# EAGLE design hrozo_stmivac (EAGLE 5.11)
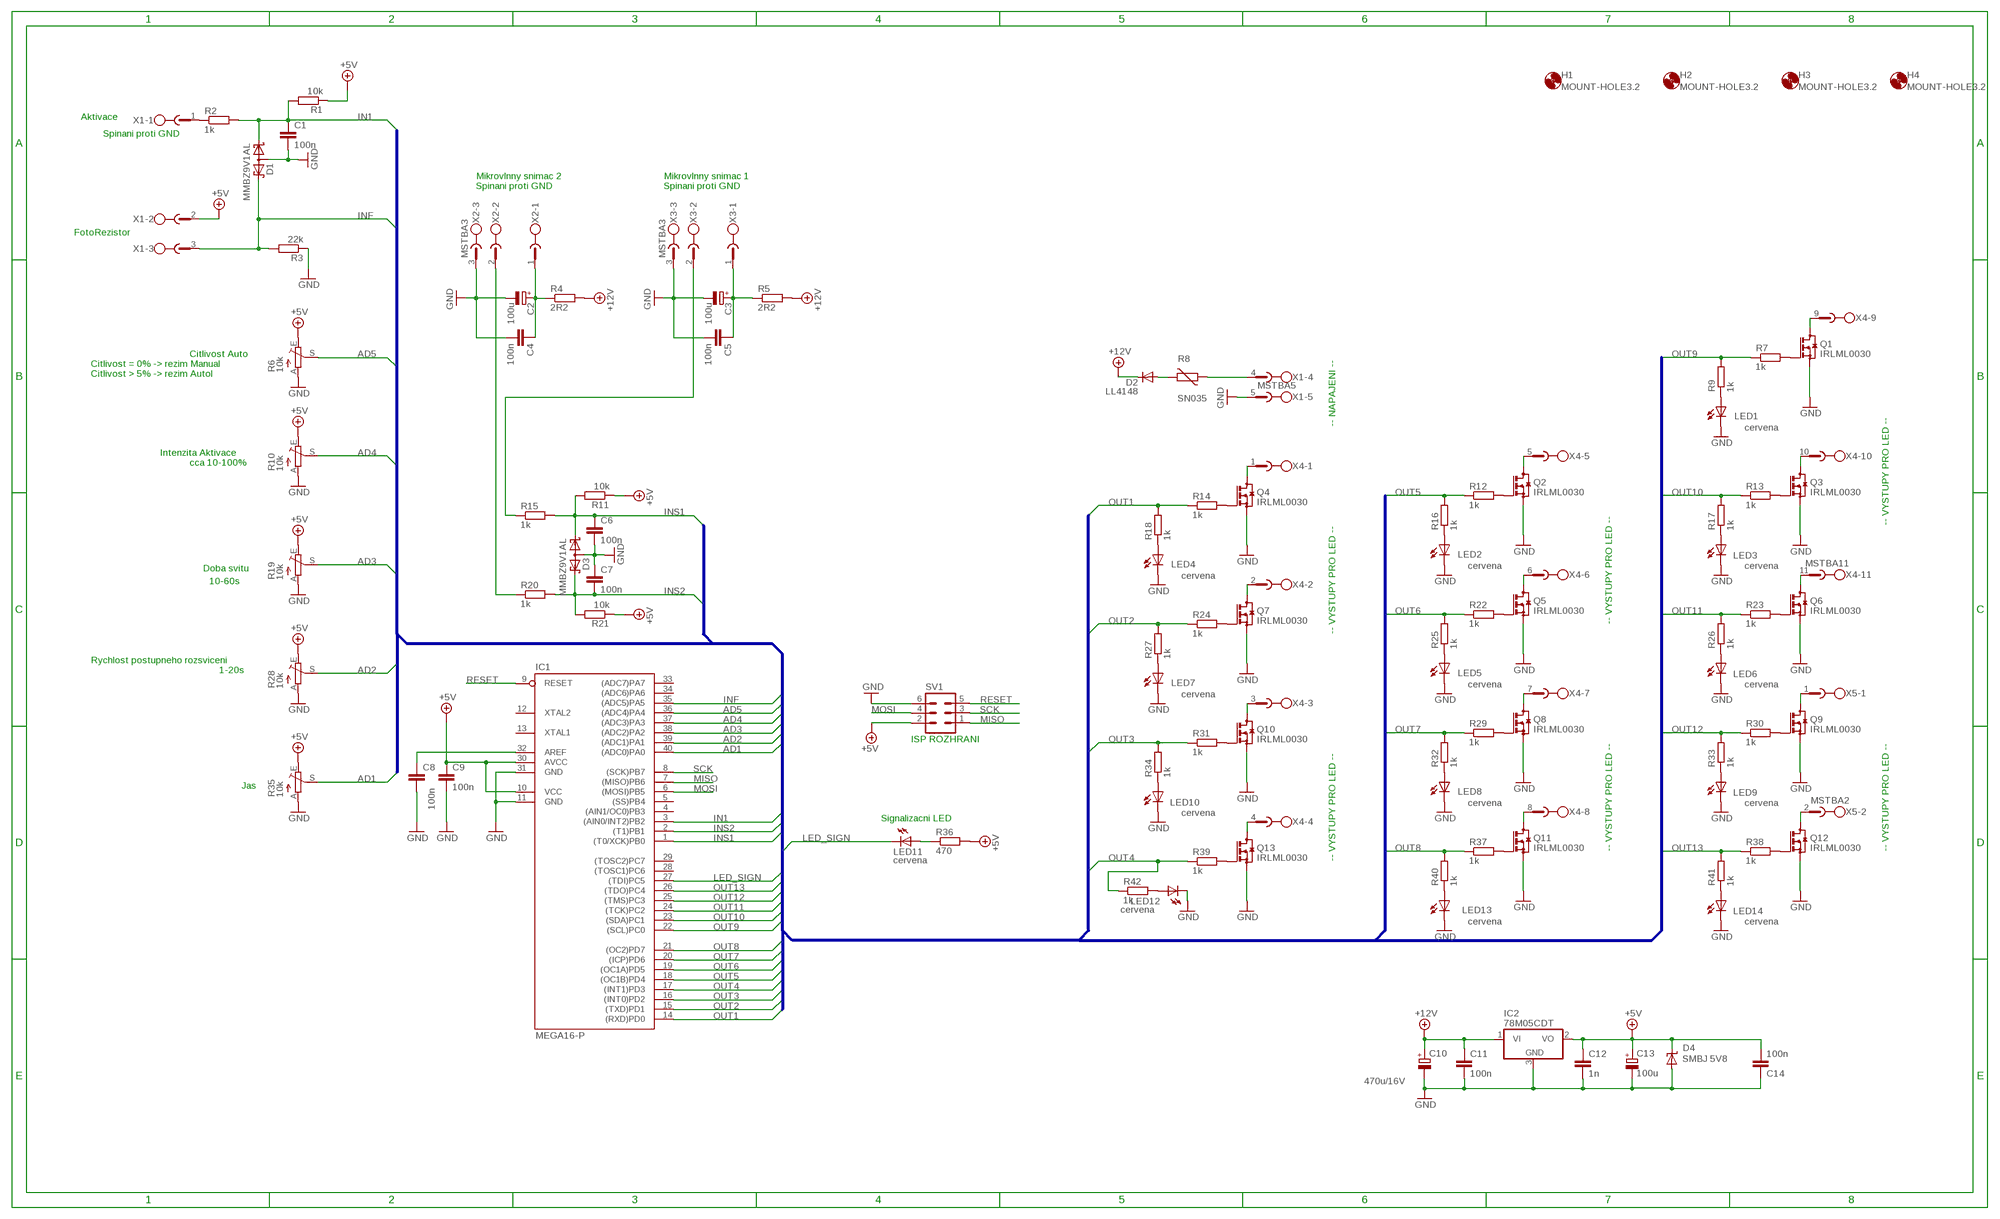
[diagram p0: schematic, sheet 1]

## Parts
C1  100n  C-EUC0805K  [C0805K]
C2  100u  CPOL-EUE2.5-5  [E2,5-5]
C3  100u  CPOL-EUE2.5-5  [E2,5-5]
C4  100n  C-EUC0805K  [C0805K]
C5  100n  C-EUC0805K  [C0805K]
C6  100n  C-EUC0805K  [C0805K]
C7  100n  C-EUC0805K  [C0805K]
C8  100n  C-EUC0805K  [C0805K]
C9  100n  C-EUC0805K  [C0805K]
C10  470u/16V  CPOL-EUE5-10.5  [E5-10,5]
C11  100n  C-EUC1206  [C1206]
C12  1n  C-EUC0805K  [C0805K]
C13  100u  CPOL-EUE2.5-5  [E2,5-5]
C14  100n  C-EUC0805  [C0805]
D1  MMBZ9V1AL  BAS40-06  [SOT23]
D2  LL4148  DIODE-MINIMELF  [MINIMELF]
D3  MMBZ9V1AL  BAS40-06  [SOT23]
D4  SMBJ 5V8  SUPPRESSOR-SMBJ  [SMBJ]
H1  MOUNT-HOLE3.2  [3,2]
H2  MOUNT-HOLE3.2  [3,2]
H3  MOUNT-HOLE3.2  [3,2]
H4  MOUNT-HOLE3.2  [3,2]
IC1  MEGA16-P  [DIL40]
IC2  78M05CDT  7805DT  [TO252]
LED1  cervena  LEDCHIPLED_0805  [CHIPLED_0805]
LED2  cervena  LEDCHIPLED_0805  [CHIPLED_0805]
LED3  cervena  LEDCHIPLED_0805  [CHIPLED_0805]
LED4  cervena  LEDCHIPLED_0805  [CHIPLED_0805]
LED5  cervena  LEDCHIPLED_0805  [CHIPLED_0805]
LED6  cervena  LEDCHIPLED_0805  [CHIPLED_0805]
LED7  cervena  LEDCHIPLED_0805  [CHIPLED_0805]
LED8  cervena  LEDCHIPLED_0805  [CHIPLED_0805]
LED9  cervena  LEDCHIPLED_0805  [CHIPLED_0805]
LED10  cervena  LEDCHIPLED_0805  [CHIPLED_0805]
LED11  cervena  LED3MM  [LED3MM]
LED12  cervena  LEDCHIPLED_0805  [CHIPLED_0805]
LED13  cervena  LEDCHIPLED_0805  [CHIPLED_0805]
LED14  cervena  LEDCHIPLED_0805  [CHIPLED_0805]
Q1  IRLML0030  BSS123  [SOT23]
Q2  IRLML0030  BSS123  [SOT23]
Q3  IRLML0030  BSS123  [SOT23]
Q4  IRLML0030  BSS123  [SOT23]
Q5  IRLML0030  BSS123  [SOT23]
Q6  IRLML0030  BSS123  [SOT23]
Q7  IRLML0030  BSS123  [SOT23]
Q8  IRLML0030  BSS123  [SOT23]
Q9  IRLML0030  BSS123  [SOT23]
Q10  IRLML0030  BSS123  [SOT23]
Q11  IRLML0030  BSS123  [SOT23]
Q12  IRLML0030  BSS123  [SOT23]
Q13  IRLML0030  BSS123  [SOT23]
R1  10k  R-EU_R0805  [R0805]
R2  1k  R-EU_R0805  [R0805]
R3  22k  R-EU_R0805  [R0805]
R4  2R2  R-EU_M1206  [M1206]
R5  2R2  R-EU_M1206  [M1206]
R6  10k  TRIM_EU-CA9V  [CA9V]
R7  1k  R-EU_R0805  [R0805]
R8  SN035  VARISTORCN1206  [CT/CN1206]
R9  1k  R-EU_R0805  [R0805]
R10  10k  TRIM_EU-CA9V  [CA9V]
R11  10k  R-EU_R0805  [R0805]
R12  1k  R-EU_R0805  [R0805]
R13  1k  R-EU_R0805  [R0805]
R14  1k  R-EU_R0805  [R0805]
R15  1k  R-EU_R0805  [R0805]
R16  1k  R-EU_R0805  [R0805]
R17  1k  R-EU_R0805  [R0805]
R18  1k  R-EU_R0805  [R0805]
R19  10k  TRIM_EU-CA9V  [CA9V]
R20  1k  R-EU_R0805  [R0805]
R21  10k  R-EU_R0805  [R0805]
R22  1k  R-EU_R0805  [R0805]
R23  1k  R-EU_R0805  [R0805]
R24  1k  R-EU_R0805  [R0805]
R25  1k  R-EU_R0805  [R0805]
R26  1k  R-EU_R0805  [R0805]
R27  1k  R-EU_R0805  [R0805]
R28  10k  TRIM_EU-CA9V  [CA9V]
R29  1k  R-EU_R0805  [R0805]
R30  1k  R-EU_R0805  [R0805]
R31  1k  R-EU_R0805  [R0805]
R32  1k  R-EU_R0805  [R0805]
R33  1k  R-EU_R0805  [R0805]
R34  1k  R-EU_R0805  [R0805]
R35  10k  TRIM_EU-CA9V  [CA9V]
R36  470  R-EU_R0805  [R0805]
R37  1k  R-EU_R0805  [R0805]
R38  1k  R-EU_R0805  [R0805]
R39  1k  R-EU_R0805  [R0805]
R40  1k  R-EU_R0805  [R0805]
R41  1k  R-EU_R0805  [R0805]
R42  1k  R-EU_R0805  [R0805]
SV1  MA03-2  [MA03-2]
X1  MSTBA5  [MSTBA5]
X2  MSTBA3  [MSTBA3]
X3  MSTBA3  [MSTBA3]
X4  MSTBA11  [MSTBA11]
X5  MSTBA2  [MSTBA2]

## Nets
+5V: C9.1 C12.1 C13.+ C14.2 D4.C IC1.10(VCC) IC1.30(AVCC) IC2.2(VO) R1.1 R6.E R10.E R11.1 R19.E R21.1 R28.E R35.E R36.2 SV1.2 X1.2
+12V: C10.+ C11.1 D2.C IC2.1(VI) R4.2 R5.2
AD1: IC1.40((ADC0)PA0) R35.S
AD2: IC1.39((ADC1)PA1) R28.S
AD3: IC1.38((ADC2)PA2) R19.S
AD4: IC1.37((ADC3)PA3) R10.S
AD5: IC1.36((ADC4)PA4) R6.S
GND: C1.2 C2.- C3.- C4.2 C5.2 C6.2 C7.1 C8.2 C9.2 C10.- C11.2 C12.2 C13.- C14.1 D1.3(AA) D3.3(AA) D4.A IC1.11(GND) IC1.31(GND) IC2.3(GND) LED1.C LED2.C LED3.C LED4.C LED5.C LED6.C LED7.C LED8.C LED9.C LED10.C LED12.C LED13.C LED14.C Q1.2(S) Q2.2(S) Q3.2(S) Q4.2(S) Q5.2(S) Q6.2(S) Q7.2(S) Q8.2(S) Q9.2(S) Q10.2(S) Q11.2(S) Q12.2(S) Q13.2(S) R3.1 R6.A R10.A R19.A R28.A R35.A SV1.6 X1.5 X2.3 X3.3
IN1: C1.1 D1.1(K1) IC1.3((AIN0/INT2)PB2) R1.2 R2.2
INF: D1.2(K2) IC1.35((ADC5)PA5) R3.2 X1.3
INS1: C6.1 D3.1(K1) IC1.1((T0/XCK)PB0) R11.2 R15.2
INS2: C7.2 D3.2(K2) IC1.2((T1)PB1) R20.2 R21.2
LED_SIGN: IC1.27((TDI)PC5) LED11.K(C)
MISO: IC1.7((MISO)PB6) SV1.1
MOSI: IC1.6((MOSI)PB5) SV1.4
N$1: R8.1 X1.4
N$2: Q4.3(D) X4.1
N$3: Q4.1(G) R14.2
N$4: Q7.1(G) R24.2
N$5: Q10.1(G) R31.2
N$6: Q13.1(G) R39.2
N$7: Q7.3(D) X4.2
N$8: Q10.3(D) X4.3
N$9: Q13.3(D) X4.4
N$10: R2.1 X1.1
N$11: R15.1 X3.2
N$12: R20.1 X2.2
N$13: LED7.A R27.1
N$14: LED12.A R42.2
N$15: D2.A R8.2
N$16: C8.1 IC1.32(AREF)
N$17: LED4.A R18.1
N$18: Q2.3(D) X4.5
N$19: Q2.1(G) R12.2
N$20: Q5.1(G) R22.2
N$21: Q8.1(G) R29.2
N$22: Q11.1(G) R37.2
N$23: Q5.3(D) X4.6
N$24: Q8.3(D) X4.7
N$25: Q11.3(D) X4.8
N$26: Q3.3(D) X4.10
N$27: Q3.1(G) R13.2
N$28: Q6.1(G) R23.2
N$29: Q9.1(G) R30.2
N$30: Q12.1(G) R38.2
N$31: Q6.3(D) X4.11
N$32: Q9.3(D) X5.1
N$33: Q12.3(D) X5.2
N$34: Q1.3(D) X4.9
N$35: Q1.1(G) R7.2
N$36: LED10.A R34.1
N$37: LED2.A R16.1
N$38: C2.+ C4.1 R4.1 X2.1
N$39: C3.+ C5.1 R5.1 X3.1
N$41: LED5.A R25.1
N$42: LED8.A R32.1
N$43: LED13.A R40.1
N$44: LED1.A R9.1
N$45: LED3.A R17.1
N$46: LED6.A R26.1
N$47: LED9.A R33.1
N$50: LED14.A R41.1
N$56: LED11.A R36.1
OUT1: IC1.14((RXD)PD0) R14.1 R18.2
OUT2: IC1.15((TXD)PD1) R24.1 R27.2
OUT3: IC1.16((INT0)PD2) R31.1 R34.2
OUT4: IC1.17((INT1)PD3) R39.1 R42.1
OUT5: IC1.18((OC1B)PD4) R12.1 R16.2
OUT6: IC1.19((OC1A)PD5) R22.1 R25.2
OUT7: IC1.20((ICP)PD6) R29.1 R32.2
OUT8: IC1.21((OC2)PD7) R37.1 R40.2
OUT9: IC1.22((SCL)PC0) R7.1 R9.2
OUT10: IC1.23((SDA)PC1) R13.1 R17.2
OUT11: IC1.24((TCK)PC2) R23.1 R26.2
OUT12: IC1.25((TMS)PC3) R30.1 R33.2
OUT13: IC1.26((TDO)PC4) R38.1 R41.2
RESET: IC1.9(RESET) SV1.5
SCK: IC1.8((SCK)PB7) SV1.3
Unconnected: IC1.4((AIN1/OC0)PB3) IC1.5((SS)PB4) IC1.12(XTAL2) IC1.13(XTAL1) IC1.28((TOSC1)PC6) IC1.29((TOSC2)PC7) IC1.33((ADC7)PA7) IC1.34((ADC6)PA6)

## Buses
OUT[1..13],IN[1..2],INS[1..2],BTN_KEYFOB,BTN_COMB,MOSI-OUT4,LED_SIGN,INF,AD[1..5]

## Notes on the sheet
- Aktivace
- Spinani proti GND
- Mikrovlnny snimac 2 | Mikrovlnny snimac 1
- Spinani proti GND | Spinani proti GND
- FotoRezistor
- Citlivost Auto
- Citlivost = 0% -> rezim Manual
- Citlivost > 5% -> rezim Autol
- -- NAPAJENI --
- Intenzita Aktivace
- cca 10-100%
- -- VYSTUPY PRO LED --
- Doba svitu
- 10-60s
- -- VYSTUPY PRO LED --
- -- VYSTUPY PRO LED --
- Rychlost postupneho rozsviceni
- 1-20s
- ISP ROZHRANI
- Jas
- Signalizacni LED
- -- VYSTUPY PRO LED -- | -- VYSTUPY PRO LED --
- -- VYSTUPY PRO LED --

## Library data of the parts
C1 C4-C9 C11 C12 C14 = rcl:C-EU: CAPACITOR, European symbol
C2 C3 C10 C13 = rcl:CPOL-EU: POLARIZED CAPACITOR, European symbol
D1 D3 = diode:BAS40-06: Silicon Schottky Diodes General-purpose diode for high-speed switching
D2 = diode:DIODE-: DIODE
D4 = diode:SUPPRESSOR-: Suppressor diode
H1-H4 = holes:MOUNT-HOLE: MOUNTING HOLE with drill center marker
IC1 = atmel:MEGA16-P: MICROCONTROLLER 16 Kbytes FLASH 1 kbytes SRAM 512 bytes EEPROM USART 8-channel 10 bit ADC Source: avr.lbr
IC2 = linear:78*: Positive VOLTAGE REGULATOR Source: http://cache.national.com/ds/LM/LM78L05.pdf http://www.fairchildsemi.com/ds/LM/LM7805.pdf
LED1-LED14 = led:LED: LED
Q1-Q13 = transistor-small-signal:BSS123: N-CHANNEL MOS FET
R1-R5 R7 R9 R11-R18 R20-R27 R29-R34 R36-R42 = rcl:R-EU_: RESISTOR, European symbol
R6 R10 R19 R28 R35 = pot:TRIM_EU-: POTENTIOMETER
R8 = varistor:VARISTOR: VARISTOR
SV1 = con-lstb:MA03-2: PIN HEADER
X1 = con-phoenix-508:MSTBA5: PHOENIX
X2 X3 = con-phoenix-508:MSTBA3: PHOENIX
X4 = con-phoenix-508:MSTBA11: PHOENIX
X5 = con-phoenix-508:MSTBA2: PHOENIX

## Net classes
2 ant: clearance 2 mm

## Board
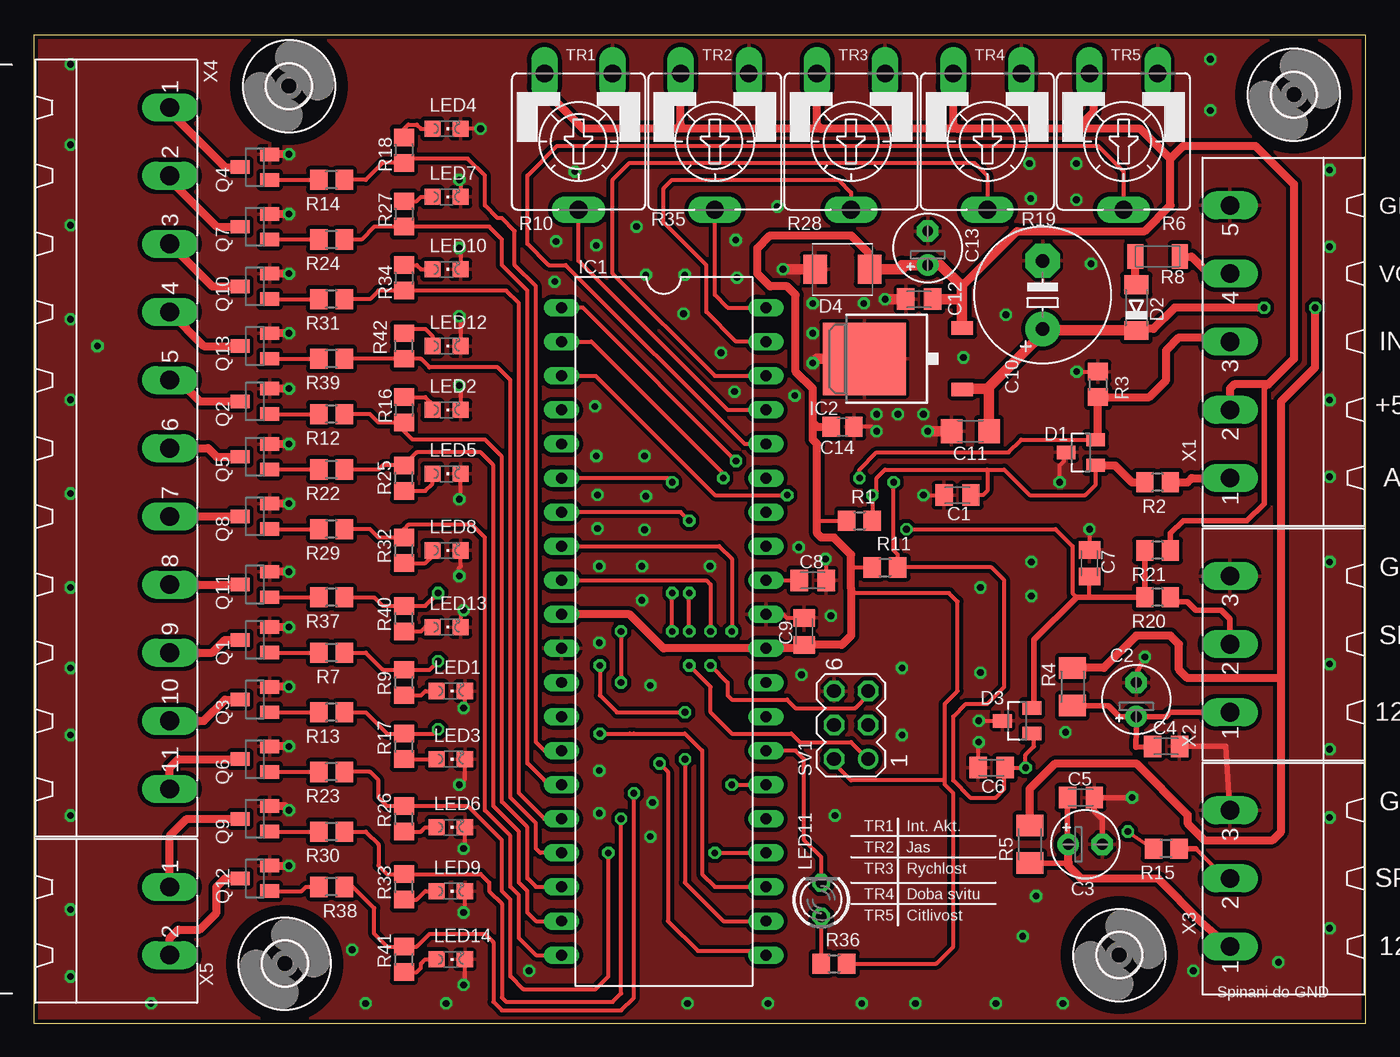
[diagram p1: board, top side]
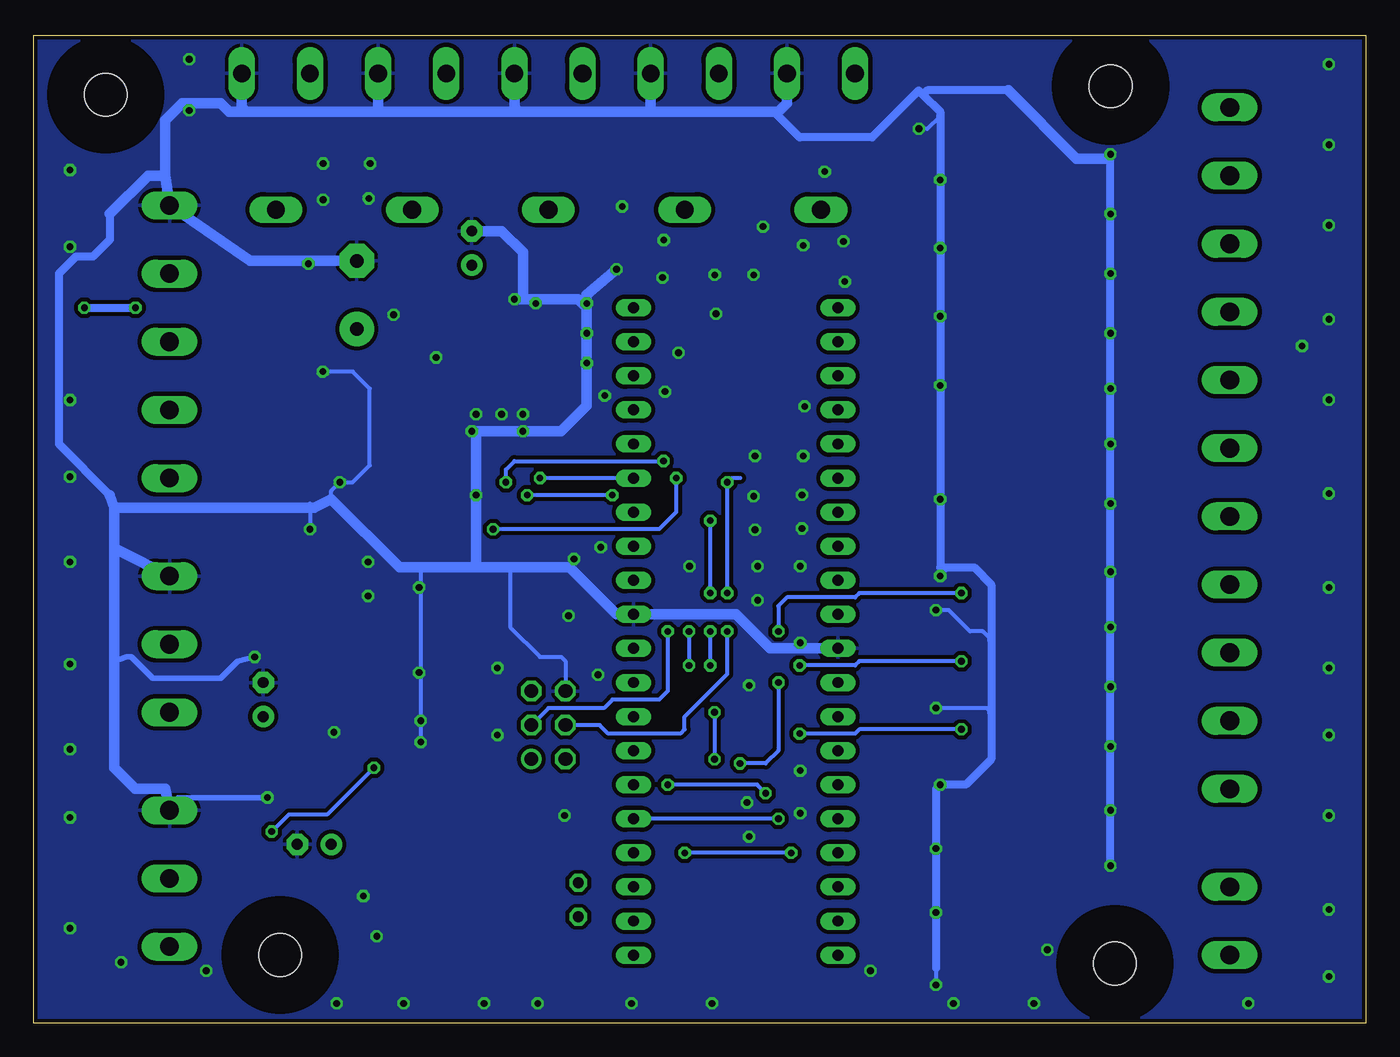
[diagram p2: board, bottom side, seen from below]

Size 99.36 x 73.65 mm. Coordinates in mm from the lower left corner, seen from the top.
Outline: 0,0 99.36,0 99.36,73.65 0,73.65 0,0
Copper layers (1*16): Top 0.035mm / dielectric 1.5mm / Bottom 0.035mm
Design rules "default *": minimum track width 0.17mm, minimum drill 0.4mm, track to track 0.2mm, track to pad 0.2mm, pad to pad 0.2mm, via to via 0.2mm, smd to smd 0.2mm, copper to edge 0.3mm, drill to drill 8mil, minimum pad ring 10mil, minimum via ring 8mil, stop-mask expansion 4mil, vias tented up to drill 0mil, thermal gap 10mil

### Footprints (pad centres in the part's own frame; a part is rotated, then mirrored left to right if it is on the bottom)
C0805K = smd 1.3 x 1.6: 1 -1,0; 2 1,0
E2,5-5 = drill 0.813 pad 1.6 round: + -1.27,0 | drill 0.813 pad 1.6 octagon: - 1.27,0
E5-10,5 = drill 1.016 pad 2.54 round: + -2.54,0 | drill 1.016 pad 2.54 octagon: - 2.54,0
C1206 = smd 1.6 x 1.8: 1 -1.4,0; 2 1.4,0
C0805 = smd 1.3 x 1.5: 1 -0.85,0; 2 0.85,0
SOT23 = smd 1 x 1.4: 1 -0.95,-1.1; 2 0.95,-1.1; 3 0,1.1
MINIMELF = smd 1.4 x 1.8: A 1.7,0; C -1.7,0
SMBJ = smd 1.78 x 2.16: A 2.04,0; C -2.03,0
3,2 = hole 3.2: 0,0
DIL40 = drill 0.813 long: 1 -24.13,-7.62; 2 -21.59,-7.62; 3 -19.05,-7.62; 4 -16.51,-7.62; 5 -13.97,-7.62; 6 -11.43,-7.62; 7 -8.89,-7.62; 8 -6.35,-7.62; 9 -3.81,-7.62; 10 -1.27,-7.62; 11 1.27,-7.62; 12 3.81,-7.62; 13 6.35,-7.62; 14 8.89,-7.62; 15 11.43,-7.62; 16 13.97,-7.62; 17 16.51,-7.62; 18 19.05,-7.62; 19 21.59,-7.62; 20 24.13,-7.62; 21 24.13,7.62; 22 21.59,7.62; 23 19.05,7.62; 24 16.51,7.62; 25 13.97,7.62; 26 11.43,7.62; 27 8.89,7.62; 28 6.35,7.62; 29 3.81,7.62; 30 1.27,7.62; 31 -1.27,7.62; 32 -3.81,7.62; 33 -6.35,7.62; 34 -8.89,7.62; 35 -11.43,7.62; 36 -13.97,7.62; 37 -16.51,7.62; 38 -19.05,7.62; 39 -21.59,7.62; 40 -24.13,7.62
TO252 = smd 1 x 1.6: 1 -2.28,-4.8; 2 2.28,-4.8 | smd 5.4 x 6.2: 3 0,2.5
CHIPLED_0805 = smd 1.2 x 1.2: A 0,-1.05; C 0,1.05
LED3MM = drill 0.813 octagon: A -1.27,0; K 1.27,0
R0805 = smd 1.3 x 1.5: 1 -0.95,0; 2 0.95,0
M1206 = smd 1.6 x 2: 1 -1.4,0; 2 1.4,0
CA9V = drill 1.321 long: A -2.54,-5.08; E 2.54,-5.08; S 0,5.08
CT/CN1206 = smd 1.2 x 1.8: 1 -1.65,0; 2 1.65,0
MA03-2 = drill 1.016 round: 1 -2.54,-1.27 | drill 1.016 octagon: 2 -2.54,1.27; 3 0,-1.27; 4 0,1.27; 5 2.54,-1.27; 6 2.54,1.27
MSTBA5 = drill 1.397 long: 1 -10.16,5.08; 2 -5.08,5.08; 3 0,5.08; 4 5.08,5.08; 5 10.16,5.08
MSTBA3 = drill 1.397 long: 1 -5.08,5.08; 2 0,5.08; 3 5.08,5.08
MSTBA11 = drill 1.397 long: 1 -25.4,5.08; 2 -20.32,5.08; 3 -15.24,5.08; 4 -10.16,5.08; 5 -5.08,5.08; 6 0,5.08; 7 5.08,5.08; 8 10.16,5.08; 9 15.24,5.08; 10 20.32,5.08; 11 25.4,5.08
MSTBA2 = drill 1.397 long: 1 -2.54,5.08; 2 2.54,5.08

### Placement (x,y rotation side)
C1  68.9,39.37 180 top
C2  82.23,24.13 90 top
C3  78.42,13.33 0 top
C4  84.45,20.64 0 top
C5  78.11,16.83 0 top
C6  71.44,19.05 180 top
C7  78.74,34.29 270 top
C8  58.1,33.02 0 top
C9  57.47,29.21 90 top
C10  75.25,54.29 90 top
C11  69.85,44.13 180 top
C12  66.04,53.97 180 top
C13  66.67,57.78 90 top
C14  60.33,44.45 180 top
D1  78.11,42.54 90 top
D2  82.23,53.34 90 top
D3  73.34,22.54 90 top
D4  60.33,56.2 180 top
H1  19.05,69.85 0 top
H2  18.73,4.45 0 top
H3  93.98,69.22 0 top
H4  80.96,5.08 0 top
IC1  46.99,29.21 270 top
IC2  64.45,49.53 90 top
LED1  31.12,24.77 270 top
LED2  30.8,45.72 270 top
LED3  31.12,19.69 270 top
LED4  30.8,66.68 270 top
LED5  30.8,40.96 270 top
LED6  31.12,14.6 270 top
LED7  30.8,61.59 270 top
LED8  30.8,35.24 270 top
LED9  31.12,9.84 270 top
LED10  30.8,56.2 270 top
LED11  58.74,9.21 90 top
LED12  30.8,50.48 270 top
LED13  30.8,29.53 270 top
LED14  31.12,4.76 270 top
Q1  16.51,28.57 90 top
Q2  16.51,46.35 90 top
Q3  16.51,24.13 90 top
Q4  16.51,63.82 90 top
Q5  16.51,42.23 90 top
Q6  16.51,19.69 90 top
Q7  16.51,59.37 90 top
Q8  16.51,37.78 90 top
Q9  16.51,15.24 90 top
Q10  16.51,54.93 90 top
Q11  16.51,32.7 90 top
Q12  16.51,10.79 90 top
Q13  16.51,50.48 90 top
R1  61.59,37.46 0 top
R2  83.82,40.32 180 top
R3  79.38,47.62 270 top
R4  77.47,25.08 90 top
R5  74.3,13.33 90 top
R6  81.28,65.72 180 top
R7  22.23,27.62 180 top
R8  83.82,57.15 180 top
R9  27.62,25.4 90 top
R10  40.64,65.72 180 top
R11  63.5,33.97 0 top
R12  22.23,45.4 180 top
R13  22.23,23.18 180 top
R14  22.23,62.86 180 top
R15  84.45,13.02 180 top
R16  27.62,45.72 270 top
R17  27.62,20.64 90 top
R18  27.62,65.09 270 top
R19  71.12,65.72 180 top
R20  83.82,31.75 180 top
R21  83.82,35.24 180 top
R22  22.23,41.27 180 top
R23  22.23,18.73 180 top
R24  22.23,58.42 180 top
R25  27.62,40.64 90 top
R26  27.62,15.24 90 top
R27  27.62,60.32 270 top
R28  60.96,65.72 180 top
R29  22.23,36.83 180 top
R30  22.23,14.29 180 top
R31  22.23,53.97 180 top
R32  27.62,35.24 90 top
R33  27.62,10.16 90 top
R34  27.62,55.56 270 top
R35  50.8,65.72 180 top
R36  59.69,4.45 0 top
R37  22.23,31.75 180 top
R38  22.23,10.16 180 top
R39  22.23,49.53 180 top
R40  27.62,30.16 90 top
R41  27.62,4.76 90 top
R42  27.62,50.48 90 top
SV1  60.96,22.23 90 top
X1  94.3,50.8 90 top
X2  94.3,28.26 90 top
X3  94.3,10.79 90 top
X4  5.08,42.86 270 top
X5  5.08,7.62 270 top

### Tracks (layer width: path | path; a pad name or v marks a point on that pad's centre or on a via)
+5V
  Top 0.3: 58.42,37.46 R1.1 | R36.2 67.31,4.45 68.58,5.71 68.58,17.14 67.95,17.78 67.95,18.1 | 67.95,18.1 67.95,23.81 68.9,24.76 68.9,31.43 68.26,32.07 61.28,32.07 60.96,32.39 | 60.96,33.97 R11.1 | SV1.2 59.69,19.37 60.96,18.1 67.95,18.1
  Top 0.4: R21.1 84.77,36.51 85.72,37.46 90.49,37.46 91.76,38.74 91.76,47.31 92.08,47.63
  Top 0.6: R10.E 38.1,69.53 40.96,66.68 47.94,66.68 | 58.74,66.68 47.94,66.68 | 68.9,66.68 58.74,66.68 | 77.79,66.68 68.9,66.68 | 77.79,66.68 79.06,67.95 79.06,70.8 R6.E | 77.79,66.68 82.55,66.68 84.77,64.45 | 84.77,64.45 84.77,60.96 82.87,59.06 73.34,59.06 69.22,54.93 | R35.E 48.26,66.99 47.94,66.68 | R28.E 58.42,66.99 58.74,66.68 | R19.E 68.58,66.99 68.9,66.68 | 84.77,64.45 85.72,65.4 91.12,65.4 93.98,62.55 93.98,49.53 92.08,47.63 89.53,47.63 89.22,47.31 X1.2 | D4.C 62.23,56.32 62.23,57.47 60.96,58.74 54.93,58.74 53.98,57.78 53.98,55.88 54.93,54.93 56.2,54.93 56.83,54.29 56.83,48.58 58.1,47.31 58.1,44.77 | 58.1,44.77 58.1,43.5 58.42,43.18 58.42,37.46 58.42,36.51 58.74,36.2 59.69,36.2 60.96,34.92 60.96,33.97 60.96,32.39 60.96,28.89 60.28,28.21 C9.1 57.2,27.94 IC1.30 46.99,27.94 44.45,30.48 IC1.10 | C14.2 58.42,44.45 58.1,44.77
  Top 0.8: 69.22,53.97 69.22,54.93 67.63,56.52 C13.+ 64.77,56.52 64.77,56.2 D4.C | 69.22,53.97 69.22,51.85 IC2.2 | 69.22,53.97 C12.1
+12V  (via drill 0.5)
  Top 0.6: R5.2 74.3,17.46 76.2,19.37 82.23,19.37 86.04,15.56 86.04,14.92 87.31,13.65 92.39,13.65 93.03,14.29 93.03,25.72 | 93.03,25.72 93.03,46.35 95.57,48.89 v95.57,53.34 | v91.76,53.34 85.09,53.34 83.5,51.75 82.34,51.75 D2.C | R4.2 79.82,26.48 82.23,28.89 84.77,28.89 85.41,28.26 85.41,26.35 86.04,25.72 93.03,25.72
  Top 0.8: D2.C 75.36,51.64 C10.+ 75.25,51.43 71.12,47.31 | 71.12,47.31 69.31,47.31 IC2.1 | C11.1 71.25,47.18 71.12,47.31
  Bottom 0.6: v95.57,53.34 v91.76,53.34
AD1
  Top 0.3: R35.S 50.8,54.29 51.75,53.34 IC1.40
AD2
  Top 0.3: IC1.39 52.39,50.8 50.16,53.02 50.16,56.52 46.99,59.69 46.99,62.23 47.62,62.86 60.01,62.86 60.96,61.91 R28.S
AD3
  Top 0.3: R19.S 71.12,63.18 70.17,64.14 44.45,64.14 43.18,62.86 43.18,55.88 50.8,48.26 IC1.38
AD4
  Top 0.3: R10.S 40.64,56.83 51.75,45.72 IC1.37
AD5
  Top 0.3: R6.S 81.28,63.5 79.37,65.4 39.05,65.4 36.83,63.18 36.83,58.1 38.42,56.52 39.69,56.52 53.02,43.18 IC1.36
GND  (via drill 0.5)
  Top 0.3: v77.78,48.57 R3.1 | 76.84,42.71 D1.3 76.84,42.38 76.84,41.91 76.52,41.59 v76.52,40.32 | v78.74,36.83 C7.1 | v66.36,39.37 C1.2 | C6.2 70.44,20.91 v70.48,20.96 | v70.48,22.54 D3.3 | C8.2 59.1,34.56 v59.06,34.61 | C9.2 56.15,30.21 55.88,30.48 IC1.31 | v33.34,66.68 LED4.C | LED7.C 31.85,62.77 v31.75,62.86 | LED10.C 31.85,57.69 v31.75,57.78 | LED12.C 31.85,52.61 v31.75,52.71 | LED2.C 31.85,47.45 v31.75,47.55 | LED5.C 31.85,39.15 v31.75,39.05 | LED8.C 31.85,34.07 31.75,33.97 v31.75,33.34 | LED13.C 31.85,30.58 v32.07,30.8 | LED1.C 32.16,23.59 v32.07,23.49 | LED3.C 32.16,18.19 v31.75,17.78 | LED6.C 32.16,13.11 v32.07,13.02 | LED9.C 32.16,8.35 v32.07,8.25 | LED14.C 32.16,2.95 v32.07,2.86 | C14.1 62.55,44.45 v62.86,44.13
  Top 0.4: C4.2 88.9,20.64 X3.3 | C2.- 82.23,26.03 v82.87,27.3 | C3.- 79.69,15.24 79.06,15.87 79.06,17.42 C5.2 v81.92,16.83
  Top 0.6: Q4.2 v19.05,64.77 | v19.05,11.75 Q12.2 | Q9.2 18.73,16.19 v19.05,15.87 | Q6.2 v19.05,20.64 | Q3.2 v19.05,25.08 | Q1.2 v19.05,29.53 | Q11.2 v19.05,33.65 | Q8.2 v19.05,38.73 v19.05,38.74 | Q5.2 v19.05,43.18 | Q2.2 v19.05,47.31 | Q13.2 v19.05,51.43 | Q10.2 v19.05,55.88 | Q7.2 v19.05,60.32
  Top 0.8: v66.67,44.13 C11.2 | v55.88,56.2 D4.A | v63.5,53.97 C12.2 | IC2.3 58.42,49.53 v58.1,49.21
  Bottom 0.3: 77.15,39.05 77.15,39.69 v76.52,40.32 75.56,40.32 74.3,41.59 74.3,47.31 75.56,48.57 v77.78,48.57 | v78.74,36.83 78.74,38.74 78.42,38.42 | v70.48,20.96 v70.48,22.54 70.48,33.97 | 59.69,33.97 v59.06,34.61 | SV1.6 59.69,26.99 60.01,27.3 61.59,27.3 63.82,29.53 63.82,33.97 | v33.34,66.68 32.7,66.68 31.75,67.63 | 31.12,33.97 v31.75,33.34 | v32.07,30.8 31.12,30.8 29.53,29.21 28.58,29.21 27.94,28.57 | v32.07,23.49 28.26,23.49 27.94,23.18 | v31.75,17.78 31.75,17.46 32.07,17.14 | 32.07,4.76 v32.07,2.86
  Bottom 0.4: v82.87,27.3 84.14,26.99 85.41,25.72 90.49,25.72 92.08,27.3 92.39,27.3 93.34,26.99 | v81.92,16.83 88.58,16.83 X3.3
  Bottom 0.6: v19.05,11.75 v19.05,15.87 v19.05,20.64 v19.05,25.08 v19.05,29.53 v19.05,33.65 v19.05,38.74 v19.05,43.18 v19.05,47.31 v19.05,51.43 v19.05,55.88 v19.05,60.32 v19.05,64.77 | 93.66,60.32 93.66,58.42 94.93,57.15 96.2,57.15 97.47,55.88 97.47,43.18 93.66,39.37 | 32.07,4.13 32.07,4.76 v32.07,8.25 v32.07,13.02 32.07,17.14 32.07,17.46 v31.75,17.78 29.84,17.78 27.94,19.69 27.94,23.18 27.94,28.57 27.94,32.7 29.21,33.97 31.12,33.97 31.75,33.97 v31.75,39.05 v31.75,47.55 v31.75,52.71 v31.75,57.78 v31.75,62.86 31.75,67.63 31.75,67.95 33.02,69.21 | 33.02,69.21 33.34,69.53 36.83,66.04 42.23,66.04 44.13,67.95 | 26.67,69.53 32.7,69.53 33.02,69.21
  Bottom 0.8: 26.67,69.53 21.59,64.45 19.37,64.45 v19.05,64.77 | 66.36,33.97 63.82,33.97 59.69,33.97 59.37,33.97 55.88,30.48 IC1.31 46.99,30.48 44.45,27.94 IC1.11 | 66.36,33.97 70.48,33.97 72.07,33.97 77.15,39.05 78.42,38.42 93.34,38.42 | 66.36,33.97 v66.36,39.37 66.36,44.13 | 93.66,39.37 93.34,38.42 | 93.66,60.32 90.81,63.18 89.53,63.18 | 89.53,63.18 X1.5 83.19,56.83 C10.- | 93.34,38.42 93.34,34.92 | 93.34,34.92 93.34,26.99 93.34,19.05 91.76,17.46 89.53,17.46 X3.3 | X2.3 93.03,35.24 93.34,34.92 | 66.36,44.13 v66.67,44.13 | 66.36,44.13 v62.86,44.13 60.01,44.13 58.1,46.04 v58.1,49.21 58.1,53.34 | 58.1,53.34 58.1,54.29 v55.88,56.2 | 62.86,53.97 58.74,53.97 58.1,53.34 | 62.86,53.97 v63.5,53.97 | C13.- 64.45,59.06 62.86,57.47 62.86,53.97 | 89.53,63.18 89.53,67.31 88.26,68.58 85.41,68.58 84.77,67.95 83.5,67.95 | 73.66,67.95 83.5,67.95 | 63.18,67.95 73.66,67.95 | 53.34,67.95 63.18,67.95 | 53.34,67.95 44.13,67.95 43.81,67.95 43.18,68.58 R10.A | 53.34,67.95 R35.A | R28.A 63.5,68.26 63.18,67.95 | 73.66,67.95 R19.A | R6.A 83.82,68.26 83.5,67.95
  other vias: 4.76,50.48 2.76,71.48 2.76,65.48 2.76,59.48 2.76,52.48 2.76,46.48 2.76,39.48 2.76,32.48 2.76,26.48 2.76,21.48 2.76,15.48 2.76,8.48 2.76,3.48 8.76,1.48 24.76,1.48 30.76,1.48 23.76,5.48 48.76,1.48 54.76,1.48 61.76,1.48 65.76,1.48 71.76,1.48 76.76,1.48 73.76,6.48 74.76,9.48 59.76,15.48 64.76,26.48 64.76,21.48 57.26,25.98 59.46,30.38 57.06,35.48 42.06,36.88 45.56,36.78 42.06,39.38 45.66,39.28 41.96,42.28 41.86,45.98 45.56,42.28 56.76,46.78 52.26,47.08 51.26,49.98 48.46,52.88 45.66,55.78 48.56,55.78 44.96,59.38 41.96,57.98 38.96,58.28 40.36,63.48 38.86,55.28 52.46,55.58 52.36,58.38 55.46,60.88 74.26,64.08 74.36,61.48 77.76,64.08 77.76,61.38 45.36,34.07 42.19,34.07 45.36,31.53 50.44,34.07 46,25.18 42.19,28.36 42.19,18.83 42.19,15.66 46,13.91 46.16,16.45 36.95,3.91 87.75,71.86 87.75,68.05 96.64,63.6 96.64,57.88 96.64,46.45 96.64,40.74 96.64,34.39 96.64,26.77 96.64,20.42 96.64,15.34 96.64,7.08 92.83,4.54 86.48,3.91 76.95,21.69 74.41,34.39 74.41,31.85 70.6,32.48 70.6,26.14 78.86,56.61 72.51,52.8 69.33,49.63 58.1,51.43 62.86,45.4 64.45,45.4 66.36,45.4 61.91,53.66 58.1,53.66
  pour Bottom (isolate 0.305): -18.1,81.28 -11.75,-12.7 111.12,-12.07 111.76,83.82
  pour Top (isolate 0.305): -8.89,-12.7 105.09,-12.7 105.73,77.47 -8.25,77.47
IN1  (via drill 0.5)
  Top 0.3: D1.1 79.2,40.15 78.42,39.37 74.3,39.37 72.39,41.28 71.12,41.28 | 71.12,41.28 63.5,41.28 62.86,40.64 62.86,39.69 v62.55,39.37 62.55,37.78 R1.2 | IC1.3 41.91,48.26 50.8,39.37 v56.2,39.37 | C1.1 70.8,39.37 71.12,39.69 71.12,41.28
  Top 0.6: R2.2 81.92,40.32 80.64,41.59 D1.1
  Bottom 0.3: v56.2,39.37 v62.55,39.37
INF  (via drill 0.5)
  Top 0.3: D1.2 73.66,43.49 72.71,42.54 62.86,42.54 61.59,41.28 v61.59,40.64
  Top 0.6: D1.2 79.37,43.67 R3.2 83.19,46.67 84.45,47.94 84.45,50.17 85.41,51.12 88.9,51.12 X1.3
  Bottom 0.3: IC1.35 v61.59,40.64
INS1  (via drill 0.5)
  Top 0.3: v81.6,14.29 R15.2 | D3.1 74.61,21.42 74.61,20.64 73.98,20 v73.98,19.05 C6.1 72.39,19 72.39,17.46 71.75,16.83 69.85,16.83 68.58,18.1 68.58,22.86 69.53,23.81 71.12,23.81 72.39,25.08 72.39,33.02 71.44,33.97 R11.2 64.45,34.92 64.14,35.24 v64.14,40.32 | IC1.1 40.96,53.34 v52.39,41.91
  Bottom 0.3: v81.6,14.29 80.33,15.56 77.47,15.56 v73.98,19.05 | v52.39,41.91 63.5,41.91 64.14,41.28 v64.14,40.32
INS2  (via drill 0.5)
  Top 0.3: IC1.2 41.59,50.8 51.44,40.96 v51.44,40.64 | v65.09,36.83 76.2,36.83 77.47,35.56 77.47,32.07 77.79,31.75 | 78.74,31.75 C7.2
  Top 0.4: R21.2 R20.2 78.74,31.75 77.79,31.75 74.61,28.57 74.61,23.66 D3.2
  Bottom 0.3: v51.44,40.64 51.44,38.1 52.7,36.83 v65.09,36.83
LED_SIGN
  Top 0.3: IC1.27 56.83,20.32 57.47,19.69 57.47,13.65 58.74,12.38 LED11.K
MISO  (via drill 0.5)
  Top 0.3: SV1.1 60.96,20.96 57.15,20.96 56.51,21.59 52.07,21.59 50.48,23.18 50.48,25.08 v48.9,26.67 | IC1.7 48.26,38.1 v48.9,37.46 | v48.9,29.21 v48.9,32.07
  Bottom 0.3: v48.9,32.07 v48.9,37.46 | v48.9,26.67 v48.9,29.21
MOSI  (via drill 0.5)  (1 unrouted)
  Top 0.3: IC1.6 47.31,40.64 v47.62,40.32 | v47.62,29.21 v47.62,32.07
  Bottom 0.3: SV1.4 57.15,22.23 56.51,21.59 51.12,21.59 50.8,21.91 50.8,22.86 47.62,26.03 v47.62,29.21 | v47.62,32.07 v47.62,40.32 | 46.67,40.64 47.31,40.64
N$1
  Top 0.6: 87.63,55.88 86.36,57.15 R8.1
  Top 0.8: 87.63,55.88 X1.4
N$2
  Top 0.6: X4.1 10.16,67.95 14.29,63.82 Q4.3
N$3
  Top 0.3: Q4.1 R14.2
N$4
  Top 0.3: Q7.1 R24.2
N$5
  Top 0.3: Q10.1 R31.2
N$6
  Top 0.3: Q13.1 R39.2
N$7
  Top 0.6: X4.2 10.16,62.86 13.65,59.37 Q7.3
N$8
  Top 0.6: X4.3 13.33,54.93 Q10.3
N$9
  Top 0.6: X4.4 12.7,50.48 Q13.3
N$10
  Top 0.6: X1.1 86.36,40.64 86.04,40.32 85.41,40.32 R2.1
N$11
  Top 0.3: X3.2 89.22,10.48 86.68,13.02
  Top 0.4: R15.1 86.68,13.02
N$12
  Top 0.4: X2.2 89.22,30.16 88.58,30.8 86.68,30.8 86.04,31.43 85.09,31.43 R20.1
N$13
  Top 0.3: LED7.A 28.89,61.6 28.58,61.28 R27.1
N$14
  Top 0.3: LED12.A 29.75,51.21 29.21,51.75 27.94,51.75 R42.2
N$15
  Top 0.6: R8.2 82.17,55.1 D2.A
  Top 0.8: D2.A 82.41,54.86
N$16
  Top 0.3: IC1.32 C8.1
N$17
  Top 0.3: LED4.A 28.89,66.68 28.58,66.99 27.94,66.99 27.62,66.68 R18.1
N$18
  Top 0.6: X4.5 10.8,47.94 12.38,46.35 Q2.3
N$19
  Top 0.3: Q2.1 R12.2
N$20
  Top 0.3: Q5.1 R22.2
N$21
  Top 0.3: Q8.1 R29.2
N$22
  Top 0.3: Q11.1 R37.2
N$23
  Top 0.6: Q5.3 13.65,42.23 13.02,42.86 X4.6
N$24
  Top 0.6: X4.7 Q8.3
N$25
  Top 0.6: X4.8 Q11.3
N$26
  Top 0.6: Q3.3 14.29,24.13 12.7,22.54 X4.10
N$27
  Top 0.3: Q3.1 R13.2
N$28
  Top 0.3: Q6.1 R23.2
N$29
  Top 0.3: Q9.1 R30.2
N$30
  Top 0.3: Q12.1 20.01,9.84 20.32,10.16 R38.2
N$31
  Top 0.6: Q6.3 10.8,19.69 10.16,19.05 X4.11
N$32
  Top 0.6: Q9.3 11.43,15.24 10.16,13.97 X5.1
N$33
  Top 0.6: Q12.3 14.29,10.8 13.65,10.16 13.65,8.25 12.38,6.99 10.8,6.99 10.16,6.35 X5.2
N$34
  Top 0.6: Q1.3 14.29,28.57 13.33,27.62 X4.9
N$35
  Top 0.3: Q1.1 R7.2
N$36
  Top 0.3: LED10.A 28.89,56.2 28.58,56.52 R34.1
N$37
  Top 0.3: LED2.A 29.75,46.14 29.21,46.67 R16.1
N$38
  Top 0.4: X2.1 84.77,23.18 84.45,22.86 C2.+ | R4.1 80.14,23.68 80.96,22.86 C2.+ | C4.1 82.19,20.59 82.23,21.91 C2.+
N$39
  Top 0.4: R5.1 77.02,11.93 77.15,12.07 | C5.1 77.11,13.38 C3.+
  Top 0.6: X3.1 87,7.62 83.82,10.8 78.11,10.8 77.15,11.75 77.15,12.07 C3.+
N$41
  Top 0.3: LED5.A 29.75,40.22 29.21,39.69 R25.1
N$42
  Top 0.3: LED8.A 29.75,34.83 29.21,34.29 R32.1
N$43
  Top 0.3: LED13.A 29.21,29.53 28.89,29.21 R40.1
N$44
  Top 0.3: LED1.A 29.21,24.76 28.89,24.45 R9.1
N$45
  Top 0.3: LED3.A R17.1
N$46
  Top 0.3: LED6.A 29.21,14.6 28.89,14.29 R26.1
N$47
  Top 0.3: LED9.A 29.21,9.84 28.58,9.21 R33.1
N$50
  Top 0.3: LED14.A 29.21,4.76 28.89,4.45 28.89,4.13 28.58,3.81 R41.1
N$56
  Top 0.3: LED11.A 58.74,6.99 R36.1
OUT1
  Top 0.3: R14.1 24.76,62.86 26.04,64.14 R18.2 27.94,64.45 32.38,64.45 33.66,63.18 33.66,60.96 34.61,60.01 34.93,60.01 35.88,59.06 35.88,56.52 37.47,54.93 37.47,20.96 38.1,20.32 IC1.14
OUT2
  Top 0.3: R24.1 24.45,58.42 25.4,59.37 R27.2 33.97,59.38 34.93,58.42 34.93,56.52 36.83,54.61 36.83,19.37 38.1,18.1 39.05,18.1 IC1.15
OUT3
  Top 0.3: R31.1 25.08,53.97 25.72,54.61 R34.2 35.24,54.61 36.19,53.66 36.19,17.14 38.1,15.24 IC1.16
OUT4
  Top 0.3: R39.1 R42.1 28.89,49.53 29.53,48.89 34.61,48.89 35.56,47.94 35.56,16.83 37.47,14.92 37.47,13.02 37.78,12.7 IC1.17
OUT5
  Top 0.3: R12.1 25.08,45.4 25.72,44.77 R16.2 27.62,44.13 28.26,43.5 33.66,43.5 34.93,42.23 34.93,16.51 36.83,14.6 36.83,10.8 37.47,10.16 IC1.18
OUT6
  Top 0.3: R22.1 25.72,41.28 26.04,41.59 R25.2 28.58,42.54 33.34,42.54 34.29,41.59 34.29,16.19 36.19,14.29 36.19,10.48 36.83,9.84 36.83,8.25 37.47,7.62 IC1.19
OUT7
  Top 0.3: R29.1 25.08,36.83 25.72,36.2 R32.2 27.62,36.83 27.94,37.15 32.7,37.15 33.66,36.2 33.66,15.87 35.56,13.97 35.56,10.16 36.19,9.52 36.19,6.35 37.47,5.08 IC1.20
OUT8  (via drill 0.5)
  Top 0.3: R37.1 25.4,31.75 26.04,31.12 R40.2 29.21,31.11 v30.16,32.07 | IC1.21 54.29,5.4 49.53,5.4 47.31,7.62 47.31,18.73 v46.67,19.37 | v43.81,29.21 v43.81,25.4
  Bottom 0.3: v30.16,32.07 37.78,32.07 38.1,31.75 43.18,31.75 43.81,31.12 v43.81,29.21 | v43.81,25.4 43.81,20.32 44.77,19.37 v46.67,19.37
OUT9  (via drill 0.5)
  Top 0.3: R7.1 24.76,27.62 26.04,26.35 R9.2 29.52,26.35 v30.16,26.99 | IC1.22 51.44,7.62 48.58,10.48 v48.58,19.69 | v48.58,23.18 43.5,23.18 42.23,24.45 v42.23,26.67
  Bottom 0.3: v30.16,26.99 37.78,26.99 38.1,26.67 v42.23,26.67 | v48.58,23.18 v48.58,19.69
OUT10  (via drill 0.5)
  Top 0.3: R13.1 24.76,23.18 26.35,21.59 R17.2 29.84,21.59 v30.16,21.91 | v42.23,21.59 44.45,21.59 | 44.45,21.59 44.77,21.59 | IC1.23 50.8,10.16 49.85,11.11 49.85,20.32 48.58,21.59 44.45,21.59
  Bottom 0.3: v30.16,21.91 37.78,21.91 38.1,21.59 v42.23,21.59
OUT11  (via drill 0.5)
  Top 0.3: R23.1 25.08,18.73 25.72,18.1 25.72,16.83 26.35,16.19 R26.2 32.39,16.19 34.93,13.65 34.93,9.84 35.56,9.21 35.56,3.49 36.51,2.54 41.91,2.54 42.86,3.49 v42.86,12.7 | v50.8,12.7 IC1.24
  Bottom 0.3: v42.86,12.7 v50.8,12.7
OUT12  (via drill 0.5)
  Top 0.3: R30.1 24.76,14.29 25.72,13.33 25.72,11.75 26.36,11.11 R33.2 33.34,11.11 33.97,10.48 33.97,9.84 34.93,8.89 34.93,1.91 35.24,1.59 43.18,1.59 43.81,2.22 v43.81,15.24
  Bottom 0.3: v43.81,15.24 IC1.25
OUT13  (via drill 0.5)
  Top 0.3: R38.1 23.81,10.16 25.4,8.57 25.4,6.67 26.35,5.71 R41.2 28.57,5.71 29.53,6.67 33.66,6.67 34.29,6.03 34.29,1.59 34.93,0.95 43.81,0.95 44.77,1.91 v44.77,17.14 | v52.07,17.78 IC1.26
  Bottom 0.3: v52.07,17.78 45.4,17.78 v44.77,17.14
RESET  (via drill 0.5)
  Top 0.3: SV1.5 62.23,24.45 61.28,23.49 56.83,23.49 56.2,24.13 52.07,24.13 51.75,24.45 51.75,25.4 v50.48,26.67 | v50.48,29.21 50.48,32.7 50.16,33.02 IC1.9
  Bottom 0.3: v50.48,29.21 v50.48,26.67
SCK  (via drill 0.5)
  Top 0.3: v52.07,29.21 52.07,34.61 51.12,35.56 IC1.8
  Bottom 0.3: SV1.3 60.96,23.49 56.83,23.49 56.2,24.13 52.7,24.13 52.07,24.76 v52.07,29.21

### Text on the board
tPlace: TR1 | TR2 | TR3 | TR4 | TR5 | GND | VCC | INF | Foto R | +5V | AKT | GND | MKS2 | Vystup LED | SP | 12V | GND | TR1 | Int. Akt. | TR2 | Jas | MKS1 | TR3 | Rychlost | TR4 | Doba svitu | SP | TR5 | Citlivost | 12V | Spinani do GND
